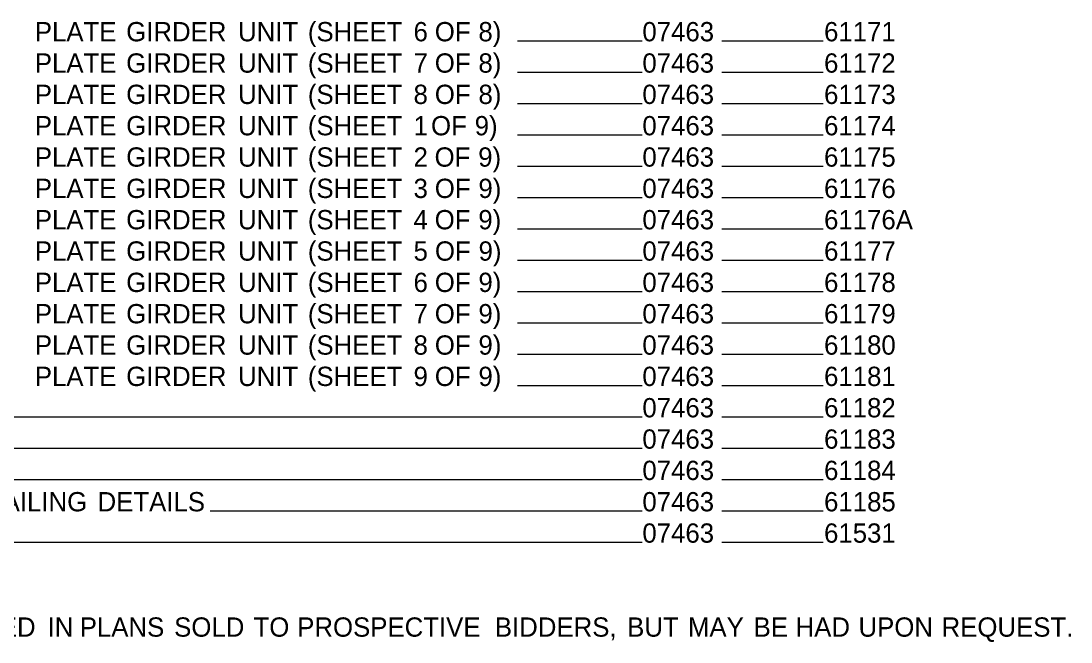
# Model space of a CAD drawing. Extents: x 2 to 32.9, y 0.7 to 21.4.
# Drawn here: x 8.57 to 17.14, y 0.99 to 6.05 of the extents above; entities that cross this region are included whole.
import ezdxf

# ---------------------------------------------------------------- set-up
doc = ezdxf.new("R2010")
doc.units = 0
doc.layers.add('Default', color=7, linetype='Continuous')

msp = doc.modelspace()

# ---------------------------------------------------------------- linework, layer by layer
at = {"layer": 'Default'}
for p, q in [((12.6184, 5.8913), (13.6355, 5.8913)), ((14.286, 5.8913), (15.1138, 5.8913)), ((12.6184, 5.6358), (13.6355, 5.6358)), ((14.286, 5.6358), (15.1138, 5.6358)), ((12.6184, 5.3802), (13.6355, 5.3802)), ((14.286, 5.3802), (15.1138, 5.3802)), ((12.6184, 5.1246), (13.6355, 5.1246)), ((14.286, 5.1246), (15.1138, 5.1246)), ((12.6184, 4.869), (13.6355, 4.869)), ((14.286, 4.869), (15.1138, 4.869)), ((12.6184, 4.6134), (13.6355, 4.6134)), ((14.286, 4.6134), (15.1138, 4.6134)), ((12.6184, 4.3578), (13.6355, 4.3578)), ((14.286, 4.3578), (15.1138, 4.3578)), ((12.6184, 4.1022), (13.6355, 4.1022)), ((14.286, 4.1022), (15.1138, 4.1022)), ((12.6184, 3.8466), (13.6355, 3.8466)), ((14.286, 3.8466), (15.1138, 3.8466)), ((12.6184, 3.591), (13.6355, 3.591)), ((14.286, 3.591), (15.1138, 3.591)), ((12.6184, 3.3354), (13.6355, 3.3354)), ((14.286, 3.3354), (15.1138, 3.3354)), ((12.6184, 3.0799), (13.6355, 3.0799)), ((14.286, 3.0799), (15.1138, 3.0799)), ((6.6412, 2.8243), (13.6355, 2.8243)), ((14.286, 2.8243), (15.1138, 2.8243)), ((5.1864, 2.5687), (13.6355, 2.5687)), ((14.286, 2.5687), (15.1138, 2.5687)), ((8.3055, 2.3131), (13.6355, 2.3131)), ((14.286, 2.3131), (15.1138, 2.3131)), ((10.1108, 2.0575), (13.6355, 2.0575)), ((14.286, 2.0575), (15.1138, 2.0575)), ((8.5089, 1.8019), (13.6355, 1.8019)), ((14.286, 1.8019), (15.1138, 1.8019))]:
    msp.add_line(p, q, dxfattribs=at)

# ---------------------------------------------------------------- texts
for s, height, p in [(' PLATE', 0.15729, (8.6222, 5.8877)), (' PLATE', 0.15729, (8.6222, 5.8877)), (' GIRDER', 0.15729, (9.3677, 5.8877)), (' GIRDER', 0.15729, (9.3677, 5.8877)), (' UNIT', 0.15729, (10.2805, 5.8877)), (' UNIT', 0.15729, (10.2805, 5.8877)), (' (SHEET', 0.15729, (10.8499, 5.8877)), (' (SHEET', 0.15729, (10.8499, 5.8877)), (' 6', 0.15729, (11.7124, 5.8877)), (' 6', 0.15729, (11.7124, 5.8877)), (' OF', 0.15729, (11.8856, 5.8877)), (' OF', 0.15729, (11.8856, 5.8877)), (' 8)', 0.15729, (12.2418, 5.8877)), (' 8)', 0.15729, (12.2418, 5.8877)), ('07463', 0.15729, (13.6381, 5.8877)), ('07463', 0.15729, (13.6381, 5.8877)), ('61171', 0.15729, (15.1205, 5.8877)), ('61171', 0.15729, (15.1205, 5.8877)), (' PLATE', 0.15729, (8.6222, 5.6321)), (' PLATE', 0.15729, (8.6222, 5.6321)), (' GIRDER', 0.15729, (9.3677, 5.6321)), (' GIRDER', 0.15729, (9.3677, 5.6321)), (' UNIT', 0.15729, (10.2805, 5.6321)), (' UNIT', 0.15729, (10.2805, 5.6321)), (' (SHEET', 0.15729, (10.8499, 5.6321)), (' (SHEET', 0.15729, (10.8499, 5.6321)), (' 7', 0.15729, (11.7124, 5.6321)), (' 7', 0.15729, (11.7124, 5.6321)), (' OF', 0.15729, (11.8856, 5.6321)), (' OF', 0.15729, (11.8856, 5.6321)), (' 8)', 0.15729, (12.2418, 5.6321)), (' 8)', 0.15729, (12.2418, 5.6321)), ('07463', 0.15729, (13.6381, 5.6321)), ('07463', 0.15729, (13.6381, 5.6321)), ('61172', 0.15729, (15.1205, 5.6321)), ('61172', 0.15729, (15.1205, 5.6321)), (' PLATE', 0.15729, (8.6222, 5.3765)), (' PLATE', 0.15729, (8.6222, 5.3765)), (' GIRDER', 0.15729, (9.3677, 5.3765)), (' GIRDER', 0.15729, (9.3677, 5.3765)), (' UNIT', 0.15729, (10.2805, 5.3765)), (' UNIT', 0.15729, (10.2805, 5.3765)), (' (SHEET', 0.15729, (10.8499, 5.3765)), (' (SHEET', 0.15729, (10.8499, 5.3765)), (' 8', 0.15729, (11.7124, 5.3765)), (' 8', 0.15729, (11.7124, 5.3765)), (' OF', 0.15729, (11.8859, 5.3765)), (' OF', 0.15729, (11.8859, 5.3765)), (' 8)', 0.15729, (12.2421, 5.3765)), (' 8)', 0.15729, (12.2421, 5.3765)), ('07463', 0.15729, (13.6381, 5.3765)), ('07463', 0.15729, (13.6381, 5.3765)), ('61173', 0.15729, (15.1205, 5.3765)), ('61173', 0.15729, (15.1205, 5.3765)), (' PLATE', 0.15729, (8.6222, 5.1209)), (' PLATE', 0.15729, (8.6222, 5.1209)), (' GIRDER', 0.15729, (9.3677, 5.1209)), (' GIRDER', 0.15729, (9.3677, 5.1209)), (' UNIT', 0.15729, (10.2805, 5.1209)), (' UNIT', 0.15729, (10.2805, 5.1209)), (' (SHEET', 0.15729, (10.8499, 5.1209)), (' (SHEET', 0.15729, (10.8499, 5.1209)), (' 1', 0.15729, (11.7124, 5.1209)), (' 1', 0.15729, (11.7124, 5.1209)), (' OF', 0.15729, (11.8552, 5.1209)), (' OF', 0.15729, (11.8552, 5.1209)), (' 9)', 0.15729, (12.2114, 5.1209)), (' 9)', 0.15729, (12.2114, 5.1209)), ('07463', 0.15729, (13.6381, 5.1209)), ('07463', 0.15729, (13.6381, 5.1209)), ('61174', 0.15729, (15.1205, 5.1209)), ('61174', 0.15729, (15.1205, 5.1209)), (' PLATE', 0.15729, (8.6222, 4.8653)), (' PLATE', 0.15729, (8.6222, 4.8653)), (' GIRDER', 0.15729, (9.3677, 4.8653)), (' GIRDER', 0.15729, (9.3677, 4.8653)), (' UNIT', 0.15729, (10.2805, 4.8653)), (' UNIT', 0.15729, (10.2805, 4.8653)), (' (SHEET', 0.15729, (10.8499, 4.8653)), (' (SHEET', 0.15729, (10.8499, 4.8653)), (' 2', 0.15729, (11.7124, 4.8653)), (' 2', 0.15729, (11.7124, 4.8653)), (' OF', 0.15729, (11.884, 4.8653)), (' OF', 0.15729, (11.884, 4.8653)), (' 9)', 0.15729, (12.2401, 4.8653)), (' 9)', 0.15729, (12.2401, 4.8653)), ('07463', 0.15729, (13.6381, 4.8653)), ('07463', 0.15729, (13.6381, 4.8653)), ('61175', 0.15729, (15.1205, 4.8653)), ('61175', 0.15729, (15.1205, 4.8653)), (' PLATE', 0.15729, (8.6222, 4.6097)), (' PLATE', 0.15729, (8.6222, 4.6097)), (' GIRDER', 0.15729, (9.3677, 4.6097)), (' GIRDER', 0.15729, (9.3677, 4.6097)), (' UNIT', 0.15729, (10.2805, 4.6097)), (' UNIT', 0.15729, (10.2805, 4.6097)), (' (SHEET', 0.15729, (10.8499, 4.6097)), (' (SHEET', 0.15729, (10.8499, 4.6097)), (' 3', 0.15729, (11.7124, 4.6097)), (' 3', 0.15729, (11.7124, 4.6097)), (' OF', 0.15729, (11.8856, 4.6097)), (' OF', 0.15729, (11.8856, 4.6097)), (' 9)', 0.15729, (12.2418, 4.6097)), (' 9)', 0.15729, (12.2418, 4.6097)), ('07463', 0.15729, (13.6381, 4.6097)), ('07463', 0.15729, (13.6381, 4.6097)), ('61176', 0.15729, (15.1205, 4.6097)), ('61176', 0.15729, (15.1205, 4.6097)), (' PLATE', 0.15729, (8.6222, 4.3542)), (' PLATE', 0.15729, (8.6222, 4.3542)), (' GIRDER', 0.15729, (9.3677, 4.3542)), (' GIRDER', 0.15729, (9.3677, 4.3542)), (' UNIT', 0.15729, (10.2805, 4.3542)), (' UNIT', 0.15729, (10.2805, 4.3542)), (' (SHEET', 0.15729, (10.8499, 4.3542)), (' (SHEET', 0.15729, (10.8499, 4.3542)), (' 4', 0.15729, (11.7124, 4.3542)), (' 4', 0.15729, (11.7124, 4.3542)), (' OF', 0.15729, (11.8849, 4.3542)), (' OF', 0.15729, (11.8849, 4.3542)), (' 9)', 0.15729, (12.2411, 4.3542)), (' 9)', 0.15729, (12.2411, 4.3542)), ('07463', 0.15729, (13.6381, 4.3542)), ('07463', 0.15729, (13.6381, 4.3542)), ('61176A', 0.15729, (15.1205, 4.3542)), ('61176A', 0.15729, (15.1205, 4.3542)), (' PLATE', 0.15729, (8.6222, 4.0986)), (' PLATE', 0.15729, (8.6222, 4.0986)), (' GIRDER', 0.15729, (9.3677, 4.0986)), (' GIRDER', 0.15729, (9.3677, 4.0986)), (' UNIT', 0.15729, (10.2805, 4.0986)), (' UNIT', 0.15729, (10.2805, 4.0986)), (' (SHEET', 0.15729, (10.8499, 4.0986)), (' (SHEET', 0.15729, (10.8499, 4.0986)), (' 5', 0.15729, (11.7124, 4.0986)), (' 5', 0.15729, (11.7124, 4.0986)), (' OF', 0.15729, (11.8868, 4.0986)), (' OF', 0.15729, (11.8868, 4.0986)), (' 9)', 0.15729, (12.243, 4.0986)), (' 9)', 0.15729, (12.243, 4.0986)), ('07463', 0.15729, (13.6381, 4.0986)), ('07463', 0.15729, (13.6381, 4.0986)), ('61177', 0.15729, (15.1205, 4.0986)), ('61177', 0.15729, (15.1205, 4.0986)), (' PLATE', 0.15729, (8.6222, 3.843)), (' PLATE', 0.15729, (8.6222, 3.843)), (' GIRDER', 0.15729, (9.3677, 3.843)), (' GIRDER', 0.15729, (9.3677, 3.843)), (' UNIT', 0.15729, (10.2805, 3.843)), (' UNIT', 0.15729, (10.2805, 3.843)), (' (SHEET', 0.15729, (10.8499, 3.843)), (' (SHEET', 0.15729, (10.8499, 3.843)), (' 6', 0.15729, (11.7124, 3.843)), (' 6', 0.15729, (11.7124, 3.843)), (' OF', 0.15729, (11.8856, 3.843)), (' OF', 0.15729, (11.8856, 3.843)), (' 9)', 0.15729, (12.2418, 3.843)), (' 9)', 0.15729, (12.2418, 3.843)), ('07463', 0.15729, (13.6381, 3.843)), ('07463', 0.15729, (13.6381, 3.843)), ('61178', 0.15729, (15.1205, 3.843)), ('61178', 0.15729, (15.1205, 3.843)), (' PLATE', 0.15729, (8.6222, 3.5874)), (' PLATE', 0.15729, (8.6222, 3.5874)), (' GIRDER', 0.15729, (9.3677, 3.5874)), (' GIRDER', 0.15729, (9.3677, 3.5874)), (' UNIT', 0.15729, (10.2805, 3.5874)), (' UNIT', 0.15729, (10.2805, 3.5874)), (' (SHEET', 0.15729, (10.8499, 3.5874)), (' (SHEET', 0.15729, (10.8499, 3.5874)), (' 7', 0.15729, (11.7124, 3.5874)), (' 7', 0.15729, (11.7124, 3.5874)), (' OF', 0.15729, (11.8856, 3.5874)), (' OF', 0.15729, (11.8856, 3.5874)), (' 9)', 0.15729, (12.2418, 3.5874)), (' 9)', 0.15729, (12.2418, 3.5874)), ('07463', 0.15729, (13.6381, 3.5874)), ('07463', 0.15729, (13.6381, 3.5874)), ('61179', 0.15729, (15.1205, 3.5874)), ('61179', 0.15729, (15.1205, 3.5874)), (' PLATE', 0.15729, (8.6222, 3.3318)), (' PLATE', 0.15729, (8.6222, 3.3318)), (' GIRDER', 0.15729, (9.3677, 3.3318)), (' GIRDER', 0.15729, (9.3677, 3.3318)), (' UNIT', 0.15729, (10.2805, 3.3318)), (' UNIT', 0.15729, (10.2805, 3.3318)), (' (SHEET', 0.15729, (10.8499, 3.3318)), (' (SHEET', 0.15729, (10.8499, 3.3318)), (' 8', 0.15729, (11.7124, 3.3318)), (' 8', 0.15729, (11.7124, 3.3318)), (' OF', 0.15729, (11.8859, 3.3318)), (' OF', 0.15729, (11.8859, 3.3318)), (' 9)', 0.15729, (12.2421, 3.3318)), (' 9)', 0.15729, (12.2421, 3.3318)), ('07463', 0.15729, (13.6381, 3.3318)), ('07463', 0.15729, (13.6381, 3.3318)), ('61180', 0.15729, (15.1205, 3.3318)), ('61180', 0.15729, (15.1205, 3.3318)), (' PLATE', 0.15729, (8.6222, 3.0762)), (' PLATE', 0.15729, (8.6222, 3.0762)), (' GIRDER', 0.15729, (9.3677, 3.0762)), (' GIRDER', 0.15729, (9.3677, 3.0762)), (' UNIT', 0.15729, (10.2805, 3.0762)), (' UNIT', 0.15729, (10.2805, 3.0762)), (' (SHEET', 0.15729, (10.8499, 3.0762)), (' (SHEET', 0.15729, (10.8499, 3.0762)), (' 9', 0.15729, (11.7124, 3.0762)), (' 9', 0.15729, (11.7124, 3.0762)), (' OF', 0.15729, (11.8859, 3.0762)), (' OF', 0.15729, (11.8859, 3.0762)), (' 9)', 0.15729, (12.2421, 3.0762)), (' 9)', 0.15729, (12.2421, 3.0762)), ('07463', 0.15729, (13.6381, 3.0762)), ('07463', 0.15729, (13.6381, 3.0762)), ('61181', 0.15729, (15.1205, 3.0762)), ('61181', 0.15729, (15.1205, 3.0762)), ('07463', 0.15729, (13.6381, 2.8206)), ('07463', 0.15729, (13.6381, 2.8206)), ('61182', 0.15729, (15.1205, 2.8206)), ('61182', 0.15729, (15.1205, 2.8206)), ('07463', 0.15729, (13.6381, 2.565)), ('07463', 0.15729, (13.6381, 2.565)), ('61183', 0.15729, (15.1205, 2.565)), ('61183', 0.15729, (15.1205, 2.565)), ('07463', 0.15729, (13.6381, 2.3094)), ('07463', 0.15729, (13.6381, 2.3094)), ('61184', 0.15729, (15.1205, 2.3094)), ('61184', 0.15729, (15.1205, 2.3094)), (' RAILING', 0.15729, (8.2078, 2.0538)), (' RAILING', 0.15729, (8.2078, 2.0538)), (' DETAILS', 0.15729, (9.1342, 2.0538)), (' DETAILS', 0.15729, (9.1342, 2.0538)), ('07463', 0.15729, (13.6381, 2.0538)), ('07463', 0.15729, (13.6381, 2.0538)), ('61185', 0.15729, (15.1205, 2.0538)), ('61185', 0.15729, (15.1205, 2.0538)), ('07463', 0.15729, (13.6381, 1.7982)), ('07463', 0.15729, (13.6381, 1.7982)), ('61531', 0.15729, (15.1205, 1.7982)), ('61531', 0.15729, (15.1205, 1.7982)), (' INCLUDED', 0.15729, (7.5533, 1.0315)), (' INCLUDED', 0.15729, (7.5533, 1.0315)), (' IN', 0.15729, (8.726, 1.0315)), (' IN', 0.15729, (8.726, 1.0315)), (' PLANS', 0.15729, (8.9887, 1.0315)), (' PLANS', 0.15729, (8.9887, 1.0315)), (' SOLD', 0.15729, (9.759, 1.0315)), (' SOLD', 0.15729, (9.759, 1.0315)), (' TO', 0.15729, (10.4067, 1.0315)), (' TO', 0.15729, (10.4067, 1.0315)), (' PROSPECTIVE', 0.157286, (10.7631, 1.0315)), (' PROSPECTIVE', 0.157286, (10.7631, 1.0315)), (' BIDDERS,', 0.15729, (12.3758, 1.0315)), (' BIDDERS,', 0.15729, (12.3758, 1.0315)), (' BUT', 0.15729, (13.4553, 1.0315)), (' BUT', 0.15729, (13.4553, 1.0315)), (' MAY', 0.15729, (13.9515, 1.0315)), (' MAY', 0.15729, (13.9515, 1.0315)), (' BE', 0.15729, (14.4872, 1.0315)), (' BE', 0.15729, (14.4872, 1.0315)), (' HAD', 0.15729, (14.8297, 1.0315)), (' HAD', 0.15729, (14.8297, 1.0315)), (' UPON', 0.15729, (15.343, 1.0315)), (' UPON', 0.15729, (15.343, 1.0315)), (' REQUEST.', 0.15729, (16.0211, 1.0315)), (' REQUEST.', 0.15729, (16.0211, 1.0315))]:
    msp.add_text(s, height=height, dxfattribs=at).set_placement(p)

doc.saveas('drawing.dxf')
